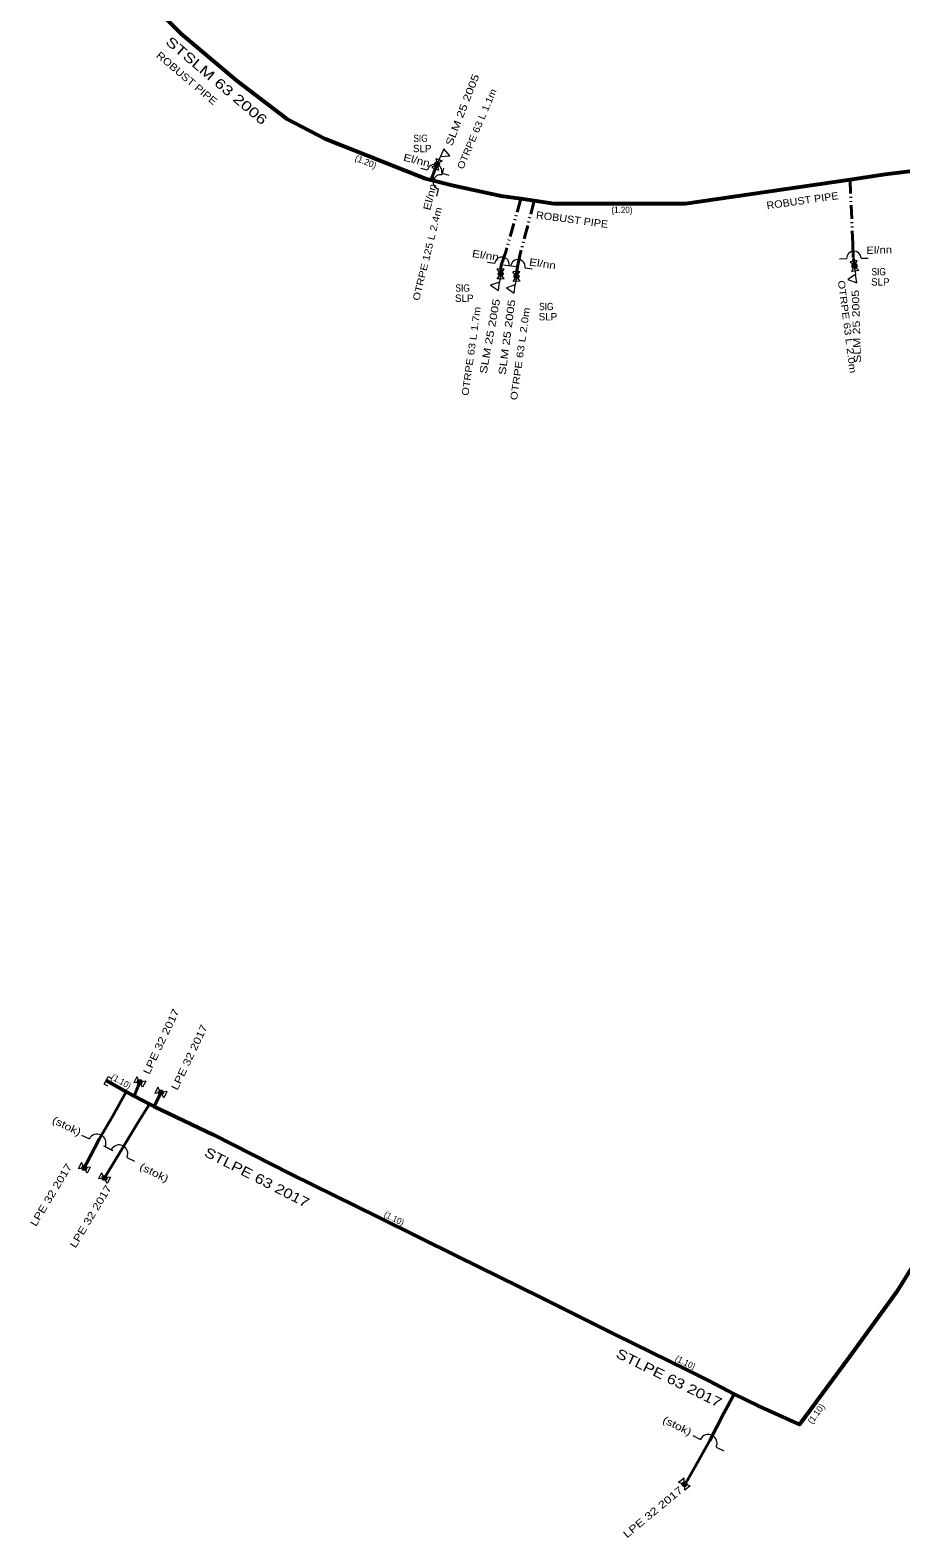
# Model space of a CAD drawing. Extents: x -648036 to -642998, y -1161549 to -1158141.
# Drawn here: x -646556.3 to -646467.2, y -1161373.5 to -1161219.3 of the extents above; entities that cross this region are included whole.
import ezdxf
from ezdxf.enums import TextEntityAlignment as Align

# ---------------------------------------------------------------- set-up
doc = ezdxf.new("R2010")
doc.units = 0
doc.header["$LTSCALE"] = 0.28
doc.linetypes.add('DASH_DOUBLE_DOT', pattern=[9.2, 5, -1.2, 0.3, -1.2, 0.3, -1.2])
for name, color, linetype, lineweight in [('12', 7, 'DASH_DOUBLE_DOT', 40), ('14', 7, 'Continuous', 13), ('15', 7, 'Continuous', 13), ('17', 7, 'Continuous', 13), ('19', 7, 'Continuous', 13), ('8', 7, 'Continuous', 53)]:
    doc.layers.add(name, color=color, linetype=linetype, lineweight=lineweight)
for name, color, linetype in [('20', 7, 'Continuous'), ('22', 7, 'Continuous'), ('24', 7, 'Continuous'), ('27', 7, 'Continuous'), ('28', 7, 'Continuous')]:
    doc.layers.add(name, color=color, linetype=linetype)

msp = doc.modelspace()

# ---------------------------------------------------------------- linework, layer by layer
at = {"layer": '12'}
for points in [[(-646515.28, -1161234.68), (-646515.14, -1161234.26), (-646514.95, -1161233.77), (-646514.75, -1161233.26), (-646514.66, -1161233.04)], [(-646472.44, -1161234.63), (-646472.15, -1161241.18), (-646472.1, -1161242.67), (-646472.02, -1161243.19), (-646471.98, -1161243.45)], [(-646506.09, -1161236.58), (-646507.63, -1161241.99), (-646508.08, -1161243.26), (-646508.14, -1161243.6), (-646508.15, -1161244.25)], [(-646504.73, -1161236.79), (-646506.15, -1161242.19), (-646506.44, -1161243.52), (-646506.55, -1161244.19), (-646506.54, -1161244.52)]]:
    msp.add_lwpolyline(points, dxfattribs=at)
at = {"layer": '12', "linetype": 'Continuous'}
for points in [[(-646545.63, -1161328.33), (-646545.23, -1161327.32), (-646545.06, -1161326.89)], [(-646546.46, -1161327.88), (-646547.86, -1161330.41), (-646549.22, -1161332.73), (-646550.5, -1161335.23), (-646550.73, -1161335.68)], [(-646543.6, -1161329.4), (-646543.08, -1161328.34), (-646542.9, -1161327.97)], [(-646544.06, -1161329.16), (-646545.21, -1161330.99), (-646546.93, -1161333.81), (-646548.39, -1161336.24), (-646548.67, -1161336.71)], [(-646484.28, -1161358.8), (-646485.33, -1161360.77), (-646486.78, -1161363.56), (-646488.44, -1161366.52), (-646489.05, -1161367.62), (-646489.37, -1161368.02)]]:
    msp.add_lwpolyline(points, dxfattribs=at)
at = {"layer": '14'}
for points in [[(-646512.99, -1161235.25), (-646514.34, -1161234.91), (-646515.28, -1161234.68)], [(-646515.14, -1161234.26), (-646514.95, -1161233.77), (-646514.75, -1161233.26)], [(-646507.63, -1161241.99), (-646508.08, -1161243.26), (-646508.14, -1161243.6)], [(-646506.15, -1161242.19), (-646506.44, -1161243.52), (-646506.55, -1161244.19)], [(-646472.15, -1161241.18), (-646472.1, -1161242.67), (-646472.02, -1161243.19)]]:
    msp.add_lwpolyline(points, dxfattribs=at)
at = {"layer": '15'}
for p, q in [((-646514.14, -1161232.708), (-646515.18, -1161233.371)), ((-646514.799, -1161232.439), (-646514.521, -1161233.641)), ((-646514.799, -1161232.439), (-646514.14, -1161232.708)), ((-646514.66, -1161233.04), (-646514.324, -1161232.252)), ((-646516.334, -1161233.432), (-646515.621, -1161233.608)), ((-646515.18, -1161233.371), (-646514.521, -1161233.641)), ((-646514.178, -1161233.966), (-646513.466, -1161234.143)), ((-646514.146, -1161234.138), (-646513.97, -1161233.425)), ((-646514.675, -1161236.295), (-646514.501, -1161235.581)), ((-646509.491, -1161243.062), (-646508.764, -1161243.165)), ((-646508.514, -1161244.748), (-646507.786, -1161243.753)), ((-646507.786, -1161243.753), (-646508.498, -1161243.741)), ((-646507.802, -1161244.759), (-646508.498, -1161243.741)), ((-646507.851, -1161243.322), (-646507.124, -1161243.425)), ((-646507.293, -1161243.378), (-646506.566, -1161243.483)), ((-646506.199, -1161244.006), (-646506.911, -1161244.027)), ((-646506.169, -1161245.013), (-646506.911, -1161244.027)), ((-646506.881, -1161245.035), (-646506.199, -1161244.006)), ((-646505.653, -1161243.638), (-646504.926, -1161243.743)), ((-646473.524, -1161242.718), (-646472.79, -1161242.695)), ((-646471.705, -1161242.899), (-646472.408, -1161243.006)), ((-646471.552, -1161243.894), (-646472.408, -1161243.006)), ((-646472.255, -1161244.002), (-646471.705, -1161242.899)), ((-646471.552, -1161243.894), (-646472.255, -1161244.002)), ((-646471.98, -1161243.45), (-646471.87, -1161244.3)), ((-646471.304, -1161242.65), (-646470.571, -1161242.629)), ((-646507.802, -1161244.759), (-646508.514, -1161244.748)), ((-646508.15, -1161244.25), (-646508.271, -1161245.098)), ((-646506.169, -1161245.013), (-646506.881, -1161245.035)), ((-646506.54, -1161244.52), (-646506.661, -1161245.368)), ((-646548.307, -1161327.312), (-646548.7, -1161327.112)), ((-646548.299, -1161326.326), (-646547.906, -1161326.527)), ((-646545.354, -1161326.348), (-646545.668, -1161326.986)), ((-646544.452, -1161326.794), (-646545.668, -1161326.986)), ((-646544.766, -1161327.432), (-646545.354, -1161326.348)), ((-646544.452, -1161326.794), (-646544.766, -1161327.432)), ((-646543.194, -1161327.428), (-646543.508, -1161328.066)), ((-646542.292, -1161327.874), (-646543.508, -1161328.066)), ((-646542.606, -1161328.512), (-646543.194, -1161327.428)), ((-646542.292, -1161327.874), (-646542.606, -1161328.512)), ((-646551.001, -1161332.328), (-646550.209, -1161332.716)), ((-646548.761, -1161333.428), (-646547.969, -1161333.816)), ((-646548.609, -1161333.502), (-646547.819, -1161333.892)), ((-646546.369, -1161334.602), (-646545.579, -1161334.992)), ((-646551.024, -1161335.138), (-646551.338, -1161335.776)), ((-646550.122, -1161335.584), (-646551.338, -1161335.776)), ((-646550.436, -1161336.222), (-646551.024, -1161335.138)), ((-646550.122, -1161335.584), (-646550.436, -1161336.222)), ((-646548.964, -1161336.168), (-646549.278, -1161336.806)), ((-646548.376, -1161337.252), (-646548.964, -1161336.168)), ((-646548.062, -1161336.614), (-646549.278, -1161336.806)), ((-646548.062, -1161336.614), (-646548.376, -1161337.252)), ((-646488.517, -1161363.04), (-646487.727, -1161363.432)), ((-646486.131, -1161364.227), (-646485.343, -1161364.62)), ((-646489.409, -1161367.405), (-646489.962, -1161367.851)), ((-646488.778, -1161368.189), (-646489.962, -1161367.851)), ((-646489.331, -1161368.635), (-646489.409, -1161367.405)), ((-646488.778, -1161368.189), (-646489.331, -1161368.635))]:
    msp.add_line(p, q, dxfattribs=at)
for points in [[(-646514.324, -1161232.252), (-646513.365, -1161232.188), (-646513.982, -1161231.451)], [(-646508.271, -1161245.098), (-646509.181, -1161245.408), (-646508.394, -1161245.96)], [(-646506.661, -1161245.368), (-646507.571, -1161245.678), (-646506.784, -1161246.23)], [(-646471.87, -1161244.3), (-646472.664, -1161244.841), (-646471.759, -1161245.163)]]:
    msp.add_lwpolyline(points, close=True, dxfattribs=at)
msp.add_lwpolyline([(-646548.7, -1161327.112), (-646548.5, -1161326.72), (-646548.299, -1161326.326)], dxfattribs=at)
for centre, radius, start, end in [((-646514.9001, -1161233.7872), 0.7431, 347.34138, 165.90609), ((-646514.323, -1161234.86), 0.7431, 77.47824, 256.04295), ((-646472.0473, -1161242.673), 0.7431, 2.99355, 181.55826), ((-646508.0286, -1161243.2721), 0.7431, 353.07082, 171.63553), ((-646506.3886, -1161243.5321), 0.7431, 353.07082, 171.63553), ((-646549.4097, -1161333.1096), 0.8917, 335.13298, 153.69769), ((-646547.1697, -1161334.2096), 0.8917, 335.13298, 153.69769), ((-646486.9297, -1161363.8296), 0.8917, 334.82325, 153.38796)]:
    msp.add_arc(centre, radius, start, end, dxfattribs=at)
at = {"layer": '17'}
for centre, radius in [((-646545.06, -1161326.89), 0.25), ((-646545.06, -1161326.89), 0.17), ((-646545.06, -1161326.89), 0.09), ((-646542.9, -1161327.97), 0.25), ((-646542.9, -1161327.97), 0.17), ((-646542.9, -1161327.97), 0.09), ((-646550.73, -1161335.68), 0.25), ((-646550.73, -1161335.68), 0.17), ((-646550.73, -1161335.68), 0.09), ((-646548.67, -1161336.71), 0.25), ((-646548.67, -1161336.71), 0.17), ((-646548.67, -1161336.71), 0.09), ((-646489.37, -1161368.02), 0.25), ((-646489.37, -1161368.02), 0.17), ((-646489.37, -1161368.02), 0.09)]:
    msp.add_circle(centre, radius, dxfattribs=at)
at = {"layer": '19'}
for centre, radius in [((-646514.66, -1161233.04), 0.25), ((-646514.66, -1161233.04), 0.17), ((-646514.66, -1161233.04), 0.09), ((-646508.15, -1161244.25), 0.25), ((-646471.98, -1161243.45), 0.25), ((-646471.98, -1161243.45), 0.17), ((-646471.98, -1161243.45), 0.09), ((-646508.15, -1161244.25), 0.17), ((-646508.15, -1161244.25), 0.09), ((-646506.54, -1161244.52), 0.25), ((-646506.54, -1161244.52), 0.17), ((-646506.54, -1161244.52), 0.09)]:
    msp.add_circle(centre, radius, dxfattribs=at)
at = {"layer": '8'}
for points in [[(-646515.28, -1161234.68), (-646515.85, -1161234.53), (-646526.08, -1161230.46), (-646529.98, -1161228.43), (-646535.18, -1161224.46), (-646540.83, -1161219.69), (-646544.89, -1161215.58), (-646549.94, -1161209.03), (-646551.24, -1161207.31), (-646552.25, -1161205.97), (-646553.06, -1161204.9), (-646554.33, -1161203.44)], [(-646420.28, -1161221.59), (-646428.53, -1161224.61), (-646437.12, -1161227.75), (-646443.11, -1161229.65), (-646452.61, -1161232.02), (-646456.34, -1161232.56), (-646468.83, -1161234.09), (-646472.44, -1161234.63)], [(-646506.09, -1161236.58), (-646508.1, -1161236.31), (-646512.99, -1161235.25), (-646514.34, -1161234.91), (-646515.28, -1161234.68)], [(-646472.44, -1161234.63), (-646489.26, -1161237.08), (-646502.73, -1161237.08), (-646504.73, -1161236.79), (-646506.09, -1161236.58)], [(-646454.09, -1161327.92), (-646455.75, -1161330.31), (-646457.01, -1161332.29), (-646459.36, -1161335.87), (-646464.86, -1161343.85), (-646467.73, -1161348.4), (-646472.48, -1161355), (-646477.62, -1161361.93), (-646481.83, -1161360.01), (-646484.28, -1161358.8), (-646486.89, -1161357.46), (-646489.05, -1161356.35), (-646496.41, -1161352.73), (-646504.05, -1161348.91), (-646512.58, -1161344.74), (-646520.67, -1161340.71), (-646529.61, -1161336.32), (-646537.52, -1161332.28), (-646543.6, -1161329.4), (-646544.06, -1161329.16), (-646545.63, -1161328.33), (-646546.46, -1161327.88), (-646548.5, -1161326.72)]]:
    msp.add_lwpolyline(points, dxfattribs=at)

# ---------------------------------------------------------------- texts
at = {"layer": '15', "width": 0.85}
for p in [(-646516.3515, -1161230.762), (-646469.5115, -1161244.401), (-646512.0465, -1161246.07), (-646503.4915, -1161247.963)]:
    msp.add_text('SIG', height=0.75, dxfattribs=at).set_placement(p, align=Align.CENTER)
at = {"layer": '15'}
for p in [(-646516.182, -1161231.806), (-646469.342, -1161245.445), (-646511.877, -1161247.114), (-646503.322, -1161249.007)]:
    msp.add_text('SLP', height=0.75, dxfattribs=at).set_placement(p, align=Align.CENTER)
at = {"layer": '20', "width": 1.35}
msp.add_text('STSLM 63 2006', height=1, rotation=319.71, dxfattribs=at).set_placement((-646537.5323, -1161224.873), align=Align.CENTER)
at = {"layer": '20', "width": 1.25}
for rotation, p in [(332.945, (-646538.559, -1161334.411)), (333.81, (-646496.459, -1161355))]:
    msp.add_text('STLPE 63 2017', height=1, rotation=rotation, dxfattribs=at).set_placement(p)
at = {"layer": '22'}
for s, rotation, width, p in [('ROBUST PIPE', 319.71, 1.15, (-646540.485, -1161224.5335)), ('SLM 25 2005', 68.755, 1.3, (-646511.7287, -1161227.6184)), ('ROBUST PIPE', 8.021, 1.1, (-646477.2458, -1161237.1247)), ('ROBUST PIPE', 352.369, 1.1, (-646500.8998, -1161239.0683)), ('SLM 25 2005', 79.641, 1.3, (-646508.8991, -1161250.6999)), ('SLM 25 2005', 82.506, 1.3, (-646507.1513, -1161250.7724)), ('SLM 25 2005', 91.673, 1.25, (-646471.419, -1161249.6114))]:
    msp.add_text(s, height=0.75, rotation=rotation, dxfattribs=dict(at, width=width)).set_placement(p, align=Align.CENTER)
for rotation, width, p in [(64.664, 1.25, (-646544.077, -1161326.188)), (64.664, 1.25, (-646541.198, -1161327.799)), (59.002, 1.25, (-646555.672, -1161341.735)), (59.002, 1.25, (-646551.627, -1161343.933)), (39.678, 1.3, (-646495.25, -1161373.572))]:
    msp.add_text('LPE 32 2017', height=0.75, rotation=rotation, dxfattribs=dict(at, width=width)).set_placement(p)
at = {"layer": '24'}
for s, rotation, width, p in [('OTRPE 63 L 1.1m', 67.036, 1.15, (-646511.99, -1161233.61)), ('OTRPE 63 L 2.0m', 277.312, 1.25, (-646473.68, -1161244.96))]:
    msp.add_text(s, height=0.7, rotation=rotation, dxfattribs=dict(at, width=width)).set_placement(p)
for s, rotation, width, p in [('OTRPE 125 L 2.4m', 76.203, 1.2, (-646514.148, -1161237.5229)), ('OTRPE 63 L 1.7m', 81.933, 1.2, (-646510.1765, -1161247.6612)), ('OTRPE 63 L 2.0m', 81.933, 1.25, (-646505.1552, -1161247.7382))]:
    msp.add_text(s, height=0.7, rotation=rotation, dxfattribs=dict(at, width=width)).set_placement(p, align=Align.RIGHT)
at = {"layer": '27'}
msp.add_text('(1.20)', height=0.65, rotation=338.045, dxfattribs=at).set_placement((-646522.074, -1161233.0785), align=Align.CENTER)
at = {"layer": '27', "width": 0.95}
msp.add_text('(1.20)', height=0.65, dxfattribs=at).set_placement((-646495.7565, -1161238.03), align=Align.CENTER)
for rotation, p in [(330.287, (-646548.053, -1161326.563)), (333.52, (-646520.164, -1161340.644)), (333.81, (-646490.391, -1161355.378))]:
    msp.add_text('(1.10)', height=0.65, rotation=rotation, dxfattribs=at).set_placement(p)
at = {"layer": '27'}
msp.add_text('(1.10)', height=0.65, rotation=53.436, dxfattribs=at).set_placement((-646476.325, -1161361.913))
at = {"layer": '28', "width": 1.2}
for rotation, p in [(346.067, (-646515.5006, -1161233.3259)), (76.203, (-646514.7048, -1161235.1429)), (351.796, (-646508.4, -1161242.9165))]:
    msp.add_text('El/nn', height=0.75, rotation=rotation, dxfattribs=at).set_placement(p, align=Align.RIGHT)
at = {"layer": '28'}
for rotation, width, p in [(1.719, 1.15, (-646470.76, -1161242.22)), (351.796, 1.2, (-646505.28, -1161243.39))]:
    msp.add_text('El/nn', height=0.75, rotation=rotation, dxfattribs=dict(at, width=width)).set_placement(p)
at = {"layer": '28', "width": 1.25}
for rotation, p in [(333.846, (-646552.6863, -1161331.7251)), (333.846, (-646543.7463, -1161336.4811)), (333.536, (-646490.2741, -1161362.3767))]:
    msp.add_text('(stok)', height=0.75, rotation=rotation, dxfattribs=at).set_placement(p, align=Align.CENTER)

doc.saveas('drawing.dxf')
